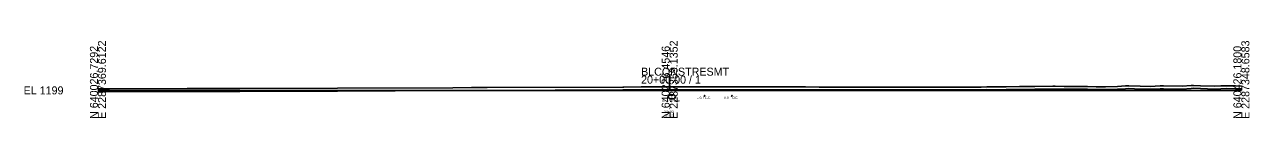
# Model space of a CAD drawing. Extents: x -26 to 3390, y -26 to 5522.
# Drawn here: x -25.7 to 402.8, y -9.7 to 17.3 of the extents above; entities that cross this region are included whole.
import ezdxf

# ---------------------------------------------------------------- set-up
doc = ezdxf.new("R2010")
doc.units = 0
for name, color, linetype in [('DR_X_Storm_Sewer', 7, 'Continuous'), ('DR_X_Text', 7, 'Continuous'), ('GK_Cells', 7, 'Continuous'), ('TX_P_5', 7, 'Continuous'), ('TX_X_5', 7, 'Continuous'), ('UT_X_Telecom', 7, 'Continuous'), ('UT_X_Telecom_Text', 7, 'Continuous'), ('XS_X_Ground_Line', 7, 'Continuous')]:
    doc.layers.add(name, color=color, linetype=linetype)

msp = doc.modelspace()

# ---------------------------------------------------------------- linework, layer by layer
at = {"layer": 'DR_X_Storm_Sewer'}
msp.add_ellipse((200.77, -2.24), major_axis=(1.25, 0), ratio=0.633333, dxfattribs=at)
at = {"layer": 'GK_Cells'}
for p, q in [((200, 0), (200, 5.15)), ((0, 0), (200, 0)), ((200, 0), (400, 0))]:
    msp.add_line(p, q, dxfattribs=at)
at = {"layer": 'UT_X_Telecom'}
for centre in [(212.21, -1.87), (221.8, -1.87)]:
    msp.add_circle(centre, 0.0833, dxfattribs=at)
at = {"layer": 'XS_X_Ground_Line'}
for points in [[(0, 0.55), (4.03, 0.57), (31.18, 0.63), (49.69, 0.64), (83.78, 0.73), (124.17, 0.94), (130.69, 0.97), (133.01, 0.98), (136.19, 0.99), (183.58, 1.18), (183.95, 1.18), (190.07, 1.19), (192.98, 1.2), (198.73, 1.21), (200, 1.21), (231.85, 1.22), (233.4, 1.22), (247.18, 1.2), (247.49, 1.19), (252.28, 1.18), (299.27, 1.16), (301.51, 1.16), (308.92, 1.15), (311.01, 1.26), (314.02, 1.23), (314.98, 1.22), (317.66, 1.26), (322.33, 1.32), (326.16, 1.34), (326.53, 1.34), (327.72, 1.37), (334, 1.44), (334.88, 1.45), (337.98, 1.37), (342.65, 1.38), (345.39, 1.37), (346.21, 1.39), (349.18, 1.28), (352.48, 1.29), (356.7, 1.41), (359.51, 1.55), (360.66, 1.63), (364.58, 1.48), (368.08, 1.37), (371.61, 1.59), (371.96, 1.6), (372.7, 1.6), (379.34, 1.43), (382.39, 1.66), (383.3, 1.72), (385.73, 1.65), (390.63, 1.48), (392.8, 1.56), (394.79, 1.62), (398, 1.54), (400, 1.52)], [(0, -0.45), (4.03, -0.43), (31.18, -0.37), (49.69, -0.36), (83.78, -0.27), (124.17, -0.06), (130.69, -0.03), (133.01, -0.02), (136.19, -0.01), (183.58, 0.18), (183.95, 0.18), (190.07, 0.19), (192.98, 0.2), (198.73, 0.21), (200, 0.21), (231.85, 0.22), (233.4, 0.22), (247.18, 0.2), (247.49, 0.19), (252.28, 0.18), (299.27, 0.16), (301.51, 0.16), (308.92, 0.15), (311.01, 0.26), (314.02, 0.23), (314.98, 0.22), (317.66, 0.26), (322.33, 0.32), (326.16, 0.34), (326.53, 0.34), (327.72, 0.37), (334, 0.44), (334.88, 0.45), (337.98, 0.37), (342.65, 0.38), (345.39, 0.37), (346.21, 0.39), (349.18, 0.28), (352.48, 0.29), (356.7, 0.41), (359.51, 0.55), (360.66, 0.63), (364.58, 0.48), (368.08, 0.37), (371.61, 0.59), (371.96, 0.6), (372.7, 0.6), (379.34, 0.43), (382.39, 0.66), (383.3, 0.72), (385.73, 0.65), (390.63, 0.48), (392.8, 0.56), (394.79, 0.62), (398, 0.54), (400, 0.52)]]:
    msp.add_lwpolyline(points, dxfattribs=at)

# ---------------------------------------------------------------- texts
at = {"layer": 'DR_X_Text'}
msp.add_text('30" X 19" RCP', height=0.7, dxfattribs=at).set_placement((197.28, -4.1))
at = {"layer": 'GK_Cells'}
for s, p in [('E 2287369.6122', (2.8, -10)), ('E 2287359.1352', (202.8, -10)), ('E 2287348.6583', (402.8, -10)), ('N 640026.7292', (0, -10)), ('N 640226.4546', (200, -10)), ('N 640426.1800', (400, -10))]:
    msp.add_text(s, height=2.8, rotation=90, dxfattribs=at).set_placement(p)
for s, p in [('20+00.00 / 1', (190, 2.35)), ('BLCONSTRESMT', (190, 5.15)), ('EL 1199', (-26, -1.4))]:
    msp.add_text(s, height=2.8, dxfattribs=at).set_placement(p)
at = {"layer": 'TX_P_5'}
for s, height, p in [('20+00', 0.85, (198.06, -7.92)), ('X', 0.7, (199.7, -6.65))]:
    msp.add_text(s, height=height, dxfattribs=at).set_placement(p)
at = {"layer": 'TX_X_5'}
msp.add_text('1200.21', height=0.7, dxfattribs=at).set_placement((198.14, -9.05))
at = {"layer": 'UT_X_Telecom_Text'}
for p in [(209.44, -2.91), (219.03, -2.91)]:
    msp.add_text('U.G. TELE.', height=0.7, dxfattribs=at).set_placement(p)

doc.saveas('drawing.dxf')
